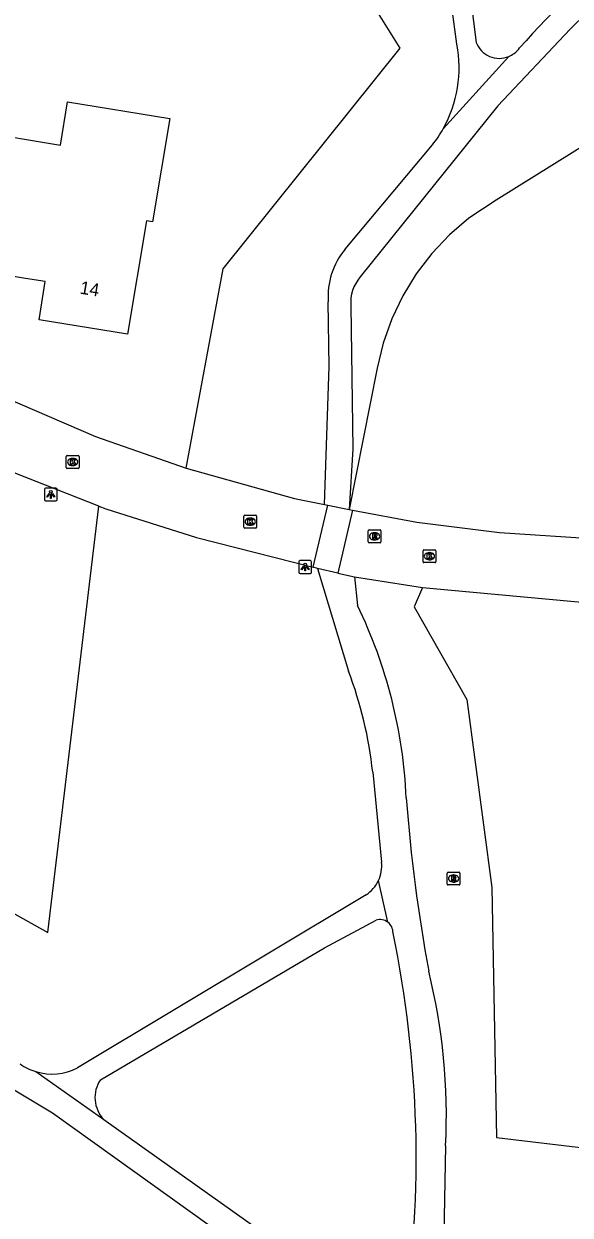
# Model space of a CAD drawing. Extents: x 163268 to 164360, y 381529 to 382285.
# Drawn here: x 163411.7 to 163454.1, y 381611.3 to 381703.8 of the extents above; entities that cross this region are included whole.
import ezdxf

# ---------------------------------------------------------------- set-up
doc = ezdxf.new("R2010")
doc.units = 0
for name, color, linetype in [('IMGEO_Groenvoorziening', 7, 'Continuous'), ('IMGEO_Kolk', 7, 'Continuous'), ('IMGEO_Lichtpunt', 7, 'Continuous'), ('IMGEO_Loofbos', 7, 'Continuous'), ('IMGEO_Pand', 7, 'Continuous'), ('IMGEO_Pand_nummerreeks', 7, 'Continuous'), ('IMGEO_Rijbaan_lokaal_open', 7, 'Continuous'), ('IMGEO_Rioolput', 7, 'Continuous'), ('IMGEO_Voetpad_halfverhard', 7, 'Continuous')]:
    doc.layers.add(name, color=color, linetype=linetype)

msp = doc.modelspace()

# ---------------------------------------------------------------- linework, layer by layer
at = {"layer": 'IMGEO_Groenvoorziening'}
msp.add_lwpolyline([(163330.491, 381679.719), (163413.518, 381633.213), (163417.487, 381666.326)], dxfattribs=at)
at = {"layer": 'IMGEO_Kolk'}
for p, q in [((163415.019, 381670.255), (163415.871, 381670.255)), ((163414.944, 381669.329), (163414.944, 381670.181)), ((163415.455, 381669.475), (163415.43, 381669.475)), ((163415.432, 381670.035), (163415.457, 381670.035)), ((163415.945, 381670.181), (163415.945, 381669.329)), ((163415.871, 381669.255), (163415.019, 381669.255)), ((163428.733, 381664.694), (163428.733, 381665.546)), ((163428.808, 381665.62), (163429.66, 381665.62)), ((163429.244, 381664.84), (163429.219, 381664.84)), ((163429.221, 381665.4), (163429.246, 381665.4)), ((163429.734, 381665.546), (163429.734, 381664.694)), ((163429.66, 381664.62), (163428.808, 381664.62)), ((163442.656, 381662.015), (163442.656, 381662.867)), ((163442.731, 381662.941), (163443.583, 381662.941)), ((163443.657, 381662.867), (163443.657, 381662.015)), ((163443.583, 381661.941), (163442.731, 381661.941)), ((163443.167, 381662.161), (163443.142, 381662.161)), ((163443.144, 381662.721), (163443.169, 381662.721))]:
    msp.add_line(p, q, dxfattribs=at)
for points in [[(163415.019, 381670.255), (163415.871, 381670.255)], [(163414.944, 381669.329), (163414.944, 381670.181)], [(163415.265, 381669.955), (163415.388, 381669.955), (163415.388, 381669.804), (163415.518, 381669.955), (163415.682, 381669.955), (163415.536, 381669.804), (163415.689, 381669.555), (163415.537, 381669.555), (163415.452, 381669.719), (163415.388, 381669.652), (163415.388, 381669.555), (163415.265, 381669.555), (163415.265, 381669.955)], [(163415.945, 381670.181), (163415.945, 381669.329)], [(163415.871, 381669.255), (163415.019, 381669.255)], [(163428.733, 381664.694), (163428.733, 381665.546)], [(163428.808, 381665.62), (163429.66, 381665.62)], [(163429.054, 381665.32), (163429.177, 381665.32), (163429.177, 381665.169), (163429.307, 381665.32), (163429.471, 381665.32), (163429.325, 381665.169), (163429.478, 381664.92), (163429.326, 381664.92), (163429.241, 381665.084), (163429.177, 381665.017), (163429.177, 381664.92), (163429.054, 381664.92), (163429.054, 381665.32)], [(163429.734, 381665.546), (163429.734, 381664.694)], [(163429.66, 381664.62), (163428.808, 381664.62)], [(163442.656, 381662.015), (163442.656, 381662.867)], [(163442.731, 381662.941), (163443.583, 381662.941)], [(163443.657, 381662.867), (163443.657, 381662.015)], [(163443.583, 381661.941), (163442.731, 381661.941)], [(163442.977, 381662.641), (163443.1, 381662.641), (163443.1, 381662.49), (163443.23, 381662.641), (163443.394, 381662.641), (163443.248, 381662.49), (163443.401, 381662.241), (163443.249, 381662.241), (163443.164, 381662.405), (163443.1, 381662.338), (163443.1, 381662.241), (163442.977, 381662.241), (163442.977, 381662.641)]]:
    msp.add_lwpolyline(points, dxfattribs=at)
for centre, start, end in [((163415.021, 381670.179), 91.55205, 178.44795), ((163415.021, 381670.179), 91.55205, 178.44795), ((163415.869, 381670.179), 1.55205, 88.44795), ((163415.869, 381670.179), 1.55205, 88.44795), ((163415.021, 381669.331), 181.55205, 268.44795), ((163415.021, 381669.331), 181.55205, 268.44795), ((163415.869, 381669.331), 271.55205, 358.44795), ((163415.869, 381669.331), 271.55205, 358.44795), ((163428.81, 381665.544), 91.55205, 178.44795), ((163428.81, 381665.544), 91.55205, 178.44795), ((163429.658, 381665.544), 1.55205, 88.44795), ((163429.658, 381665.544), 1.55205, 88.44795), ((163428.81, 381664.696), 181.55205, 268.44795), ((163428.81, 381664.696), 181.55205, 268.44795), ((163429.658, 381664.696), 271.55205, 358.44795), ((163429.658, 381664.696), 271.55205, 358.44795), ((163442.733, 381662.865), 91.55205, 178.44795), ((163442.733, 381662.865), 91.55205, 178.44795), ((163443.581, 381662.865), 1.55205, 88.44795), ((163443.581, 381662.865), 1.55205, 88.44795), ((163442.733, 381662.017), 181.55205, 268.44795), ((163442.733, 381662.017), 181.55205, 268.44795), ((163443.581, 381662.017), 271.55205, 358.44795), ((163443.581, 381662.017), 271.55205, 358.44795)]:
    msp.add_arc(centre, 0.0765, start, end, dxfattribs=at)
for centre, major_axis, ratio, start_param, end_param in [((163415.431, 381669.755), (-0.387, 0.002), 0.722429, 4.712389, 7.853982), ((163415.456, 381669.755), (-0.39, 0.002), 0.717154, 1.570796, 4.712389), ((163429.22, 381665.12), (-0.387, 0.002), 0.722429, 4.712389, 7.853982), ((163429.245, 381665.12), (-0.39, 0.002), 0.717154, 1.570796, 4.712389), ((163443.143, 381662.441), (-0.387, 0.002), 0.722429, 4.712389, 7.853982), ((163443.168, 381662.441), (-0.39, 0.002), 0.717154, 1.570796, 4.712389)]:
    msp.add_ellipse(centre, major_axis=major_axis, ratio=ratio, start_param=start_param, end_param=end_param, dxfattribs=at)
at = {"layer": 'IMGEO_Lichtpunt'}
for p, q in [((163413.245, 381667.64), (163413.245, 381666.833)), ((163413.245, 381667.64), (163413.245, 381666.833)), ((163414.147, 381667.735), (163413.339, 381667.735)), ((163414.147, 381667.735), (163413.339, 381667.735)), ((163414.241, 381666.833), (163414.241, 381667.64)), ((163414.241, 381666.833), (163414.241, 381667.64)), ((163413.339, 381666.739), (163414.147, 381666.739)), ((163413.339, 381666.739), (163414.147, 381666.739)), ((163433.008, 381662), (163433.008, 381661.193)), ((163433.008, 381662), (163433.008, 381661.193)), ((163433.91, 381662.095), (163433.102, 381662.095)), ((163433.91, 381662.095), (163433.102, 381662.095)), ((163434.004, 381661.193), (163434.004, 381662)), ((163434.004, 381661.193), (163434.004, 381662)), ((163433.102, 381661.099), (163433.91, 381661.099)), ((163433.102, 381661.099), (163433.91, 381661.099))]:
    msp.add_line(p, q, dxfattribs=at)
for points in [[(163413.619, 381667.304), (163413.658, 381667.276), (163413.47, 381667.014), (163413.432, 381667.041), (163413.619, 381667.304)], [(163413.721, 381667.256), (163413.768, 381667.256), (163413.768, 381666.934), (163413.721, 381666.934), (163413.721, 381667.256)], [(163413.831, 381667.276), (163413.869, 381667.303), (163414.056, 381667.041), (163414.017, 381667.013), (163413.831, 381667.276)], [(163433.382, 381661.664), (163433.421, 381661.636), (163433.233, 381661.374), (163433.195, 381661.401), (163433.382, 381661.664)], [(163433.484, 381661.616), (163433.531, 381661.616), (163433.531, 381661.294), (163433.484, 381661.294), (163433.484, 381661.616)], [(163433.594, 381661.636), (163433.632, 381661.663), (163433.819, 381661.401), (163433.78, 381661.373), (163433.594, 381661.636)]]:
    msp.add_lwpolyline(points, dxfattribs=at)
for centre in [(163413.744, 381667.438), (163433.507, 381661.798)]:
    msp.add_circle(centre, 0.0994, dxfattribs=at)
for centre, start, end in [((163413.339, 381667.64), 90, 180), ((163413.339, 381667.64), 90, 180), ((163414.147, 381667.64), 0, 90), ((163414.147, 381667.64), 0, 90), ((163413.339, 381666.833), 180, 270), ((163413.339, 381666.833), 180, 270), ((163414.147, 381666.833), 270, 0), ((163414.147, 381666.833), 270, 360), ((163433.102, 381662), 90, 180), ((163433.102, 381662), 90, 180), ((163433.91, 381662), 0, 90), ((163433.91, 381662), 0, 90), ((163433.102, 381661.193), 180, 270), ((163433.102, 381661.193), 180, 270), ((163433.91, 381661.193), 270, 0), ((163433.91, 381661.193), 270, 360)]:
    msp.add_arc(centre, 0.0946, start, end, dxfattribs=at)
at = {"layer": 'IMGEO_Loofbos'}
for points in [[(163515.932, 381725.699), (163500, 381718.416), (163478.019, 381708.509), (163458.768, 381696.586), (163448.335, 381690.097), (163446.223, 381688.687), (163444.708, 381687.392), (163443.337, 381685.945), (163442.124, 381684.363), (163441.084, 381682.663), (163440.227, 381680.864), (163439.563, 381678.984), (163439.099, 381677.046), (163436.908, 381666.064)], [(163424.267, 381669.269), (163427.133, 381684.771), (163440.874, 381701.897), (163439.197, 381704.593), (163437.035, 381707.052), (163434.791, 381709.023), (163429.21, 381711.228), (163426.855, 381711.053)], [(163442.602, 381660.009), (163441.974, 381658.511), (163446.05, 381651.319), (163447.993, 381636.708), (163448.357, 381617.306), (163459.913, 381615.932), (163467.608, 381615.147), (163500.109, 381607.374), (163500.96, 381607.171), (163500.848, 381606.174), (163534.27, 381588.252), (163555.584, 381575.614)]]:
    msp.add_lwpolyline(points, dxfattribs=at)
at = {"layer": 'IMGEO_Pand'}
msp.add_lwpolyline([(163414.488, 381694.376), (163415.052, 381697.731), (163422.979, 381696.425), (163421.641, 381688.408), (163421.172, 381688.485), (163419.707, 381679.675), (163412.852, 381680.79), (163413.315, 381683.775), (163411.785, 381684.019), (163406.237, 381684.903), (163407.975, 381695.449), (163414.488, 381694.376)], dxfattribs=at)
at = {"layer": 'IMGEO_Rijbaan_lokaal_open'}
for points in [[(163336.795, 381717.345), (163351.762, 381712.267), (163355.051, 381710.889), (163362.159, 381707.029), (163367.988, 381703.121), (163372.635, 381699.671), (163382.632, 381691.621), (163388.244, 381687.318), (163394.839, 381682.863), (163400.907, 381679.343), (163408.849, 381675.346), (163417.211, 381671.729), (163424.267, 381669.269)], [(163417.487, 381666.326), (163408.435, 381669.883), (163403.317, 381672.32), (163396.047, 381676.226), (163390.269, 381679.724), (163382.665, 381685.191), (163365.756, 381698.629), (163363.185, 381700.457), (163356.936, 381704.332), (163350.46, 381707.4), (163339.976, 381711.167), (163336.032, 381712.46)], [(163424.267, 381669.269), (163432.675, 381666.933), (163435.001, 381666.457)], [(163417.487, 381666.326), (163418.018, 381666.117), (163425.073, 381663.899), (163434.132, 381661.576)], [(163434.132, 381661.576), (163435.271, 381666.401)], [(163435.001, 381666.457), (163435.271, 381666.401)], [(163435.271, 381666.401), (163436.908, 381666.064)], [(163437.182, 381666.013), (163436.031, 381661.135)], [(163436.908, 381666.064), (163437.182, 381666.013)], [(163437.182, 381666.013), (163442.176, 381665.079), (163448.608, 381664.27), (163455.329, 381663.829), (163457.86, 381663.79), (163462.224, 381663.302), (163472.048, 381661.348), (163476.829, 381659.912)], [(163434.459, 381661.492), (163434.132, 381661.576)], [(163436.031, 381661.135), (163434.459, 381661.492)], [(163436.031, 381661.135), (163437.328, 381660.841)], [(163437.328, 381660.841), (163442.602, 381660.009)], [(163442.602, 381660.009), (163460.334, 381658.369), (163466.34, 381657.437), (163470.435, 381656.592), (163477.242, 381654.553), (163480.719, 381653.221), (163483.709, 381651.834), (163487.738, 381649.717), (163494.209, 381645.839)]]:
    msp.add_lwpolyline(points, dxfattribs=at)
at = {"layer": 'IMGEO_Rioolput'}
for p, q in [((163438.389, 381663.555), (163438.389, 381664.407)), ((163438.464, 381664.481), (163439.316, 381664.481)), ((163438.877, 381664.261), (163438.902, 381664.261)), ((163439.39, 381664.407), (163439.39, 381663.555)), ((163439.316, 381663.481), (163438.464, 381663.481)), ((163438.9, 381663.701), (163438.875, 381663.701)), ((163444.598, 381637.908), (163445.45, 381637.908)), ((163444.523, 381636.982), (163444.523, 381637.834)), ((163445.034, 381637.128), (163445.009, 381637.128)), ((163445.011, 381637.688), (163445.036, 381637.688)), ((163445.524, 381637.834), (163445.524, 381636.982)), ((163445.45, 381636.908), (163444.598, 381636.908))]:
    msp.add_line(p, q, dxfattribs=at)
for points in [[(163438.389, 381663.555), (163438.389, 381664.407)], [(163438.464, 381664.481), (163439.316, 381664.481)], [(163438.978, 381664.179), (163438.726, 381664.181), (163438.726, 381663.781)], [(163438.726, 381663.781), (163438.85, 381663.781), (163438.85, 381663.943), (163438.861, 381663.943)], [(163438.904, 381664.1), (163438.85, 381664.1), (163438.85, 381664.019)], [(163438.85, 381664.019), (163438.902, 381664.019)], [(163438.908, 381663.914), (163438.979, 381663.781), (163439.119, 381663.781), (163439.054, 381663.907)], [(163439.39, 381664.407), (163439.39, 381663.555)], [(163439.316, 381663.481), (163438.464, 381663.481)], [(163444.598, 381637.908), (163445.45, 381637.908)], [(163444.523, 381636.982), (163444.523, 381637.834)], [(163445.112, 381637.606), (163444.86, 381637.608), (163444.86, 381637.208)], [(163444.86, 381637.208), (163444.984, 381637.208), (163444.984, 381637.37), (163444.995, 381637.37)], [(163445.038, 381637.527), (163444.984, 381637.527), (163444.984, 381637.446)], [(163444.984, 381637.446), (163445.036, 381637.446)], [(163445.042, 381637.341), (163445.113, 381637.208), (163445.253, 381637.208), (163445.188, 381637.334)], [(163445.524, 381637.834), (163445.524, 381636.982)], [(163445.45, 381636.908), (163444.598, 381636.908)]]:
    msp.add_lwpolyline(points, dxfattribs=at)
for centre, radius, start, end in [((163438.466, 381664.405), 0.0765, 91.55205, 178.44795), ((163438.466, 381664.405), 0.0765, 91.55205, 178.44795), ((163438.86, 381663.89), 0.0533, 26.02933, 88.69889), ((163438.886, 381664.208), 0.19, 274.7715, 282.96867), ((163438.91, 381664.004), 0.0964, 77.00612, 93.18647), ((163438.924, 381664.061), 0.0378, 276.66336, 79.67722), ((163438.977, 381664.069), 0.109, 350.36119, 89.41601), ((163438.975, 381664.069), 0.112, 277.58423, 350.98172), ((163438.959, 381663.854), 0.108, 29.51342, 73.79051), ((163439.314, 381664.405), 0.0765, 1.55205, 88.44795), ((163439.314, 381664.405), 0.0765, 1.55205, 88.44795), ((163438.466, 381663.557), 0.0765, 181.55205, 268.44795), ((163438.466, 381663.557), 0.0765, 181.55205, 268.44795), ((163439.314, 381663.557), 0.0765, 271.55205, 358.44795), ((163439.314, 381663.557), 0.0765, 271.55205, 358.44795), ((163444.6, 381637.832), 0.0765, 91.55205, 178.44795), ((163444.6, 381637.832), 0.0765, 91.55205, 178.44795), ((163445.448, 381637.832), 0.0765, 1.55205, 88.44795), ((163445.448, 381637.832), 0.0765, 1.55205, 88.44795), ((163444.6, 381636.984), 0.0765, 181.55205, 268.44795), ((163444.6, 381636.984), 0.0765, 181.55205, 268.44795), ((163444.994, 381637.317), 0.0533, 26.02933, 88.69889), ((163445.02, 381637.635), 0.19, 274.7715, 282.96867), ((163445.044, 381637.431), 0.0964, 77.00612, 93.18647), ((163445.058, 381637.488), 0.0378, 276.66336, 79.67722), ((163445.111, 381637.496), 0.109, 350.36119, 89.41601), ((163445.109, 381637.496), 0.112, 277.58423, 350.98172), ((163445.093, 381637.281), 0.108, 29.51342, 73.79051), ((163445.448, 381636.984), 0.0765, 271.55205, 358.44795), ((163445.448, 381636.984), 0.0765, 271.55205, 358.44795)]:
    msp.add_arc(centre, radius, start, end, dxfattribs=at)
for centre, major_axis, ratio, start_param, end_param in [((163438.876, 381663.981), (-0.387, 0.002), 0.722429, 4.712389, 7.853982), ((163438.901, 381663.981), (-0.39, 0.002), 0.717154, 1.570796, 4.712389), ((163445.01, 381637.408), (-0.387, 0.002), 0.722429, 4.712389, 7.853982), ((163445.035, 381637.408), (-0.39, 0.002), 0.717154, 1.570796, 4.712389)]:
    msp.add_ellipse(centre, major_axis=major_axis, ratio=ratio, start_param=start_param, end_param=end_param, dxfattribs=at)
at = {"layer": 'IMGEO_Voetpad_halfverhard'}
for points in [[(163445.279, 381702.201), (163443.737, 381713.823)], [(163445.302, 381713.994), (163446.789, 381702.347)], [(163454.084, 381703.371), (163448.47, 381697.417), (163437.765, 381684.127)], [(163449.323, 381701.252), (163444.225, 381695.637)], [(163436.603, 381686.279), (163443.39, 381694.388)], [(163435.001, 381666.457), (163435.362, 381677.163), (163435.29, 381682.2)], [(163437.045, 381681.891), (163437.217, 381670.781), (163436.908, 381666.064)], [(163434.459, 381661.492), (163436.867, 381653.511)], [(163437.328, 381660.841), (163437.569, 381658.604)], [(163438.809, 381600.427), (163438.464, 381600.706), (163429.218, 381608.183), (163413.891, 381619.182), (163386.457, 381635.598), (163366.682, 381647.039)], [(163438.747, 381645.667), (163439.442, 381638.687)], [(163439.923, 381634.013), (163439.189, 381637.245)], [(163438.234, 381636.136), (163415.812, 381622.711)], [(163417.601, 381621.782), (163435.005, 381632.012), (163439.006, 381634.167)], [(163412.592, 381622.409), (163417.865, 381618.696)], [(163417.865, 381618.696), (163431.009, 381609.349), (163439.636, 381602.534)], [(163444.41, 381616.638), (163444.142, 381602.797), (163443.987, 381601.37), (163443.755, 381599.241)]]:
    msp.add_lwpolyline(points, dxfattribs=at)
for centre, radius, start, end in [((163524.381, 381631.519), 100.521, 120.97533, 134.37308), ((163515.383, 381643.193), 87.773, 122.38287, 138.00382), ((163435.807, 381700.355), 9.65, 330.72946, 11.02599), ((163448.583, 381703.02), 1.916, 200.5492, 292.71022), ((163448.589, 381703.011), 1.905, 306.96935, 325.0598), ((163448.55, 381703.073), 1.978, 293.01014, 306.80857), ((163435.879, 381700.313), 9.567, 321.73238, 330.73941), ((163441.061, 381682.593), 5.784, 140.41694, 183.89709), ((163440.205, 381682.107), 3.168, 140.38686, 183.91566), ((163403.237, 381641.959), 38.154, 2.56437, 25.86522), ((163407.77, 381642.39), 31.149, 6.0388, 20.91731), ((163563.193, 381652.67), 122.172, 184.22645, 190.5934), ((163436.698, 381638.425), 2.757, 334.64888, 5.44852), ((163436.69, 381638.431), 2.766, 303.92807, 334.60607), ((163439.316, 381633.207), 1.009, 53.02447, 107.90906), ((163439.318, 381633.206), 1.008, 358.22014, 53.14631), ((163355.613, 381615.618), 86.513, 351.65799, 11.70925), ((163397.248, 381618.945), 47.219, 357.19935, 13.80203), ((163413.834, 381626.504), 4.279, 234.8019, 253.12134), ((163413.832, 381626.507), 4.282, 253.16928, 297.54678), ((163419.614, 381620.4), 2.442, 145.52206, 224.25717)]:
    msp.add_arc(centre, radius, start, end, dxfattribs=at)

# ---------------------------------------------------------------- texts
at = {"layer": 'IMGEO_Pand_nummerreeks'}
msp.add_text('14', height=1, rotation=350.76146, dxfattribs=at).set_placement((163415.958, 381682.838))

doc.saveas('drawing.dxf')
